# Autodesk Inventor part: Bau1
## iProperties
Shininess: 64.0
Length Units: 11269
Angle Units: 11279
Time Units: 11290
Mass Units: 11283
Length Display Precision: 3
Angle Display Precision: 2
Compacted: True
Part Number: Bau1
Document SubType Name: Modeling
Created: 2003-07
Material: Standard
Designer: Michael
Manufacturer: Standard
Standards Organization: Custom
Density: 0.0
Volumn: 0.0
Area: 0.0
PropertySet Name: Model Information
Control State: 0
Master: False
Checked Out: False
Author: Michael
